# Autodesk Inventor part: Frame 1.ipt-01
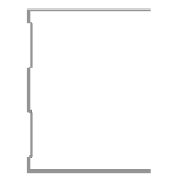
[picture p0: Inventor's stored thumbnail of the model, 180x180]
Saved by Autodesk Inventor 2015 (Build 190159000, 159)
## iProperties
Created: 2015-04
Part Number: Frame 1.ipt-01
Material: Aluminum 6061
Document SubType Name: Modeling
Standard: Unnamed
Designer: suporte
Language: en-US
Size Designation: (Unnamed 1)
Categories: <MemberInstance><Categories><Category DisplayName="Structural Shapes" InternalName="089c4875-fa83-4c05-b084-43b9cc11f5ed" Mnemonic="GRDR"><CategoryParameter Dis
Density: 2.7 g/cm^3
Appearance: Aluminum - Flat
IsCustomPart: 1
G_L: 1054,820 mm
G_W: 70,000 mm
G_H: 75,000 mm
+C6D07C4E-F784-4905-9E85-D001DAC4732C+CUTDETAIL1: Miter 67,49 deg
_CCFamilyMember: 1
_CCFamilyDisplayName: Frame 1
_FrameMemberDoc: Frame Member File
_Version: 15.0.0
_GetPNFromCC: 1
Author: suporte
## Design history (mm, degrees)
node "Start Plane"
node "End Plane"
sketch "Sketch"
  geometry: L1 (34.6, 37.5)-(34.6, 36.7); L2 (34.6, 36.7)-(-34.6, 36.7); L3 (-34.6, -36.7)-(34.6, -36.7); L4 (34.6, -36.7)-(34.6, -37.5); L5 (34.6, -37.5)-(-35.4, -37.5); L6 (-35.4, 37.5)-(34.6, 37.5); L7 (-34.6, 36.7)-(-34.6, 31.7); L8 (-34.6, 31.7)-(-33.4, 30.5); L9 (-33.4, 30.5)-(-33.4, 10.746); L10 (-33.4, 10.746)-(-34.6, 9.546); L11 (-34.6, 9.546)-(-34.6, -9.546); L12 (-34.6, -9.546)-(-33.4, -10.746); L13 (-33.4, -10.746)-(-33.4, -30.5); L14 (-33.4, -30.5)-(-34.6, -31.7); L15 (-34.6, -31.7)-(-34.6, -36.7); L16 (-35.4, -37.5)-(-35.4, -31.369); L17 (-35.4, -31.369)-(-34.2, -30.169); L18 (-34.2, -30.169)-(-34.2, -11.077); L19 (-34.2, -11.077)-(-35.4, -9.877); L20 (-35.4, -9.877)-(-35.4, 9.877); L21 (-35.4, 9.877)-(-34.2, 11.077); L22 (-34.2, 11.077)-(-34.2, 30.169); L23 (-34.2, 30.169)-(-35.4, 31.369); L24 (-35.4, 31.369)-(-35.4, 37.5); L25 (-35.4, 0)-(30.37, 0); 3 further points
  constraints: 50 end point, 10 point on line, 9 parallel, 5 perpendicular, 4 equal length, 3 midpoint, 3 vertical, 2 vertical alignment, 1 collinear, 1 horizontal, 1 horizontal alignment
  dimensions: "d3" = 0.8 distance of L1.start L1.end; "d5" = 75 distance between parallel lines of L5 L6; "d6" = 0.8 distance between parallel lines of L24 L7; "d7" = 0.8 distance between parallel lines of L8 L23; "d8" = 0.8 distance between parallel lines of L22 L9; "d9" = 0.8 distance between parallel lines of L17 L14; "d10" = 0.8 distance between parallel lines of L13 L18; "d11" = 0.8 distance between parallel lines of L12 L19; "d12" = 0.8 distance between parallel lines of L21 L10; "d13" = 5 distance of L2.end L7.end; "d15" = 135 deg angle of L9 L8; "d16" = 2 distance between parallel lines of L24 L9; "d17" = 70 distance of L6.start L1.start
extrude "Body" join sketch "Sketch" stored distance "d24" = 0.13; taper "d25" = 0 deg
node "Driven Length"
  sketch "Sketch8"
    geometry: L1 (0, 0)-(10, 0) reference
    constraints: 2 end point, 1 horizontal
  workplane "Work Plane6"
  sketch "Sketch9"
    geometry: L1 (-2, 0)-(12, 0) reference; L2 (-2, 1054.82)-(12, 1054.82) reference
    dimensions: "d27" = 1054.81978 distance between parallel lines of L1 L2 (derived)
workplane "Work Plane7"
split "Split1"
body "Solid1"
other parameters: "tamanho" = 1018.55826, "G_OFFSET_START" = 0 [user parameter; used in 1 equation term], "G_OFFSET_END" = 36.26152 [user parameter; used in 1 equation term], "d22" = 0 (computed from G_OFFSET_START), "d23" = 1054.81978 (= tamanho + G_OFFSET_END), "G_L" = 1054.81978 (= d27) [user parameter], "d32" = 90 deg
